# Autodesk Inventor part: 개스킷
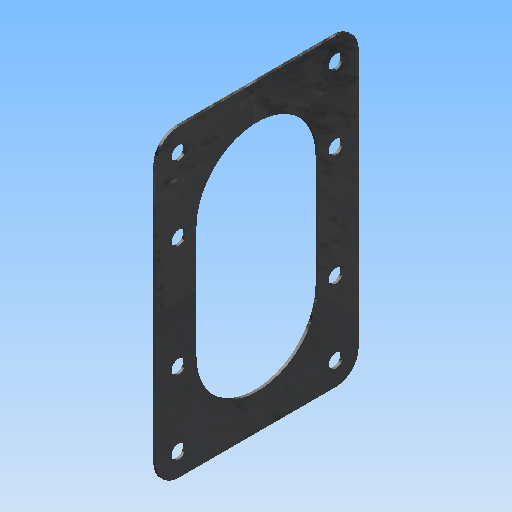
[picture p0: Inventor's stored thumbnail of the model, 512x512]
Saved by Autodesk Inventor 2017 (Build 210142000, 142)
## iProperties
Created: 2019-03
Part Number: 개스킷
Material: 고무
Document SubType Name: Modeling
Designer: mduedu
Density: 1 g/cm^3
Appearance: 고무 - 검은색 - 버전 1.1
Author: mduedu
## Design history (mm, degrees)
sketch "스케치1"
  geometry: L1 (-60, 40)-(60, 40); L2 (60, 40)-(60, -40); L3 (60, -40)-(-60, -40); L4 (-60, -40)-(-60, 40); L5 (-60, 40)-(60, -40); L6 (60, 40)-(-60, -40); 1 further point
  constraints: 12 end point, 2 midpoint, 2 parallel, 1 horizontal, 1 perpendicular
  dimensions: "d21" = 120 distance of L2.end L3.end; "d22" = 80 distance of L1.end L2.end
extrude "돌출1" new body sketch "스케치1" distance "d3" = 1; taper "d4" = 0 deg
fillet "모깎기1" dims "d5" = 9
sketch "스케치2" dims "d6" = 48
  geometry: L1 (-24, -22)-(24, -22); L2 (24, -22)-(24, 22); L3 (24, 22)-(-24, 22); L4 (-24, 22)-(-24, -22); L5 (-24, -22)-(24, 22); L6 (24, -22)-(-24, 22); 3 further points
  constraints: 12 end point, 4 midpoint, 2 horizontal alignment, 2 parallel, 1 horizontal, 1 perpendicular, 4 other
  dimensions: "d8" = 22 distance from line of L3 point (0, 0)
extrude "돌출2" cut sketch "스케치2" stored distance "d9" = 1; taper "d10" = 0 deg
sketch "스케치3"
  geometry: L1 (-24, -22)-(-24, 22) reference; L2 (24, 22)-(24, -22) reference; L3 (40, -51)-(40, 51) reference; L4 (31, 60)-(-31, 60) reference; L5 (-40, 51)-(-40, -51) reference; L6 (-31, -60)-(31, -60) reference; L7 (-31, 51)-(31, 51); L8 (31, 51)-(31, -51); L9 (31, -51)-(-31, -51); L10 (-31, -51)-(-31, 51); A1 r 24 centre (0, 22) between (24, 22) and (-24, 22) reference; A2 r 24 centre (0, -22) between (-24, -22) and (24, -22) reference; A3 r 9 centre (31, -51) between (31, -60) and (40, -51) reference; A4 r 9 centre (31, 51) between (40, 51) and (31, 60) reference; A5 r 9 centre (-31, 51) between (-31, 60) and (-40, 51) reference; A6 r 9 centre (-31, -51) between (-40, -51) and (-31, -60) reference; 9 further points
  constraints: 8 end point, 4 coincident, 4 horizontal alignment, 4 point on line, 2 parallel, 1 horizontal, 1 perpendicular
  dimensions: "d23" = 102 distance between parallel lines of L9 L7 (derived); "d24" = 29 distance from line of point (-31, 22) L7 (derived); "d25" = 29 distance from line of point (-31, -22) L9 (derived)
hole "구멍1" sketch "스케치3" at (-31, 51), (31, 51), (31, -51), (-31, -51), (-31, -22), (-31, 22), (31, 22), (31, -22) diameter "d14" = 5.5; stored, may be unused: countersink angle "d18" = 90 deg, drill point angle "d20" = 118 deg; dims "d15" = 6, "d16" = 4, "d17" = 2, "d19" = 8
node "솔리드1"
node "투영된 루프1"
